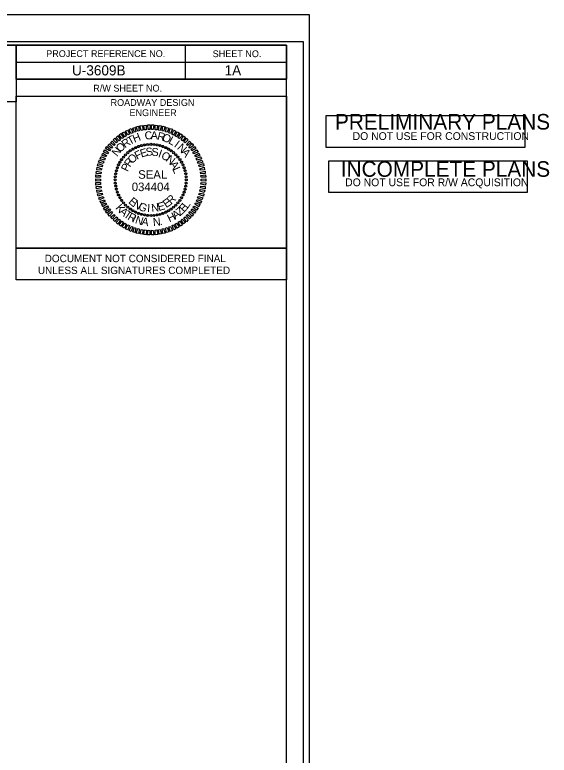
# Model space of a CAD drawing. Extents: x 1877070 to 1879304, y 464355 to 465670.
# Drawn here: x 1878829 to 1879304, y 465012 to 465670 of the extents above; entities that cross this region are included whole.
import ezdxf

# ---------------------------------------------------------------- set-up
doc = ezdxf.new("R2010")
doc.units = 0
for name, color, linetype in [('Prop AutoTurn Projected Path', 7, 'Continuous'), ('Prop Conc 2ft 6in Curb and Gutter', 7, 'Continuous'), ('Prop EOT', 7, 'Continuous'), ('Prop Horizontal Alignment', 7, 'Continuous'), ('Prop Horizontal Alignment Direction Label', 7, 'Continuous'), ('Prop Horizontal Alignment Tick Label', 7, 'Continuous'), ('Prop Horizontal Alignment Tick Small', 7, 'Continuous'), ('Prop Lane Lines', 7, 'Continuous'), ('Scratch_Level_0', 7, 'Continuous'), ('Scratch_Level_6', 7, 'Continuous')]:
    doc.layers.add(name, color=color, linetype=linetype)

# ---------------------------------------------------------------- blocks, each defined once
blk = doc.blocks.new('STICKER PRELIMINARY PLANS')
at = {"layer": 'Prop Horizontal Alignment Direction Label'}
blk.add_lwpolyline([(0, -0.47), (0, 0), (2.94, 0), (2.94, -0.47)], close=True, dxfattribs=at)
for s, height, p in [('PRELIMINARY PLANS', 0.2304, (0.13, -0.207)), ('DO NOT USE FOR CONSTRUCTION', 0.1152, (0.392, -0.361))]:
    blk.add_text(s, height=height, dxfattribs=at).set_placement(p)

msp = doc.modelspace()

# ---------------------------------------------------------------- linework, layer by layer
at = {"layer": 'Prop AutoTurn Projected Path'}
msp.add_lwpolyline([(1877069.97, 464355.13), (1879090.77, 464355.13), (1879090.77, 465669.52), (1877069.97, 465669.52)], close=True, dxfattribs=at)
at = {"layer": 'Prop Conc 2ft 6in Curb and Gutter'}
for p, q in [((1878938.83, 465552.69), (1878938.83, 465552.69)), ((1878941.47, 465553.5), (1878941.47, 465553.5)), ((1878944.23, 465554.05), (1878944.23, 465554.05)), ((1878946.93, 465554.47), (1878946.93, 465554.47)), ((1878949.7, 465554.59), (1878949.7, 465554.59)), ((1878952.47, 465554.45), (1878952.47, 465554.45)), ((1878955.19, 465554.05), (1878955.19, 465554.05)), ((1878957.84, 465553.53), (1878957.84, 465553.53)), ((1878960.5, 465552.7), (1878960.5, 465552.7)), ((1878927.31, 465545.31), (1878927.31, 465545.31)), ((1878929.36, 465547.24), (1878929.36, 465547.24)), ((1878931.53, 465548.85), (1878931.53, 465548.85)), ((1878933.9, 465550.34), (1878933.9, 465550.34)), ((1878936.33, 465551.64), (1878936.33, 465551.64)), ((1878963.04, 465551.61), (1878963.04, 465551.61)), ((1878965.52, 465550.39), (1878965.52, 465550.39)), ((1878967.81, 465548.86), (1878967.81, 465548.86)), ((1878970.05, 465547.19), (1878970.05, 465547.19)), ((1878972.03, 465545.34), (1878972.03, 465545.34)), ((1878922.26, 465538.8), (1878922.26, 465538.8)), ((1878923.79, 465541.09), (1878923.79, 465541.09)), ((1878925.46, 465543.33), (1878925.46, 465543.33)), ((1878973.96, 465543.29), (1878973.96, 465543.29)), ((1878975.57, 465541.12), (1878975.57, 465541.12)), ((1878977.06, 465538.75), (1878977.06, 465538.75)), ((1878919.95, 465533.78), (1878919.95, 465533.78)), ((1878921.04, 465536.32), (1878921.04, 465536.32)), ((1878978.36, 465536.32), (1878978.36, 465536.32)), ((1878979.41, 465533.81), (1878979.41, 465533.81)), ((1878918.2, 465525.75), (1878918.2, 465525.75)), ((1878918.6, 465528.47), (1878918.6, 465528.47)), ((1878919.12, 465531.12), (1878919.12, 465531.12)), ((1878980.22, 465531.18), (1878980.22, 465531.18)), ((1878980.77, 465528.42), (1878980.77, 465528.42)), ((1878981.19, 465525.72), (1878981.19, 465525.72)), ((1878918.06, 465522.98), (1878918.06, 465522.98)), ((1878918.18, 465520.21), (1878918.18, 465520.21)), ((1878981.16, 465520.18), (1878981.16, 465520.18)), ((1878981.3, 465522.95), (1878981.3, 465522.95)), ((1878918.6, 465517.51), (1878918.6, 465517.51)), ((1878919.15, 465514.75), (1878919.15, 465514.75)), ((1878980.25, 465514.81), (1878980.25, 465514.81)), ((1878980.77, 465517.46), (1878980.77, 465517.46)), ((1878919.95, 465512.12), (1878919.95, 465512.12)), ((1878921.01, 465509.62), (1878921.01, 465509.62)), ((1878922.31, 465507.18), (1878922.31, 465507.18)), ((1878977.11, 465507.13), (1878977.11, 465507.13)), ((1878978.32, 465509.61), (1878978.32, 465509.61)), ((1878979.41, 465512.15), (1878979.41, 465512.15)), ((1878923.8, 465504.81), (1878923.8, 465504.81)), ((1878925.41, 465502.64), (1878925.41, 465502.64)), ((1878927.34, 465500.59), (1878927.34, 465500.59)), ((1878972.06, 465500.62), (1878972.06, 465500.62)), ((1878973.91, 465502.6), (1878973.91, 465502.6)), ((1878975.57, 465504.84), (1878975.57, 465504.84)), ((1878929.32, 465498.74), (1878929.32, 465498.74)), ((1878931.56, 465497.08), (1878931.56, 465497.08)), ((1878933.85, 465495.54), (1878933.85, 465495.54)), ((1878936.33, 465494.32), (1878936.33, 465494.32)), ((1878938.87, 465493.24), (1878938.87, 465493.24)), ((1878960.53, 465493.24), (1878960.53, 465493.24)), ((1878963.03, 465494.29), (1878963.03, 465494.29)), ((1878965.47, 465495.59), (1878965.47, 465495.59)), ((1878967.84, 465497.08), (1878967.84, 465497.08)), ((1878970.01, 465498.69), (1878970.01, 465498.69)), ((1878941.53, 465492.4), (1878941.53, 465492.4)), ((1878944.18, 465491.88), (1878944.18, 465491.88)), ((1878946.9, 465491.49), (1878946.9, 465491.49)), ((1878949.67, 465491.35), (1878949.67, 465491.35)), ((1878952.44, 465491.46), (1878952.44, 465491.46)), ((1878955.14, 465491.88), (1878955.14, 465491.88)), ((1878957.9, 465492.43), (1878957.9, 465492.43))]:
    msp.add_line(p, q, dxfattribs=at)
for points in [[(1878944.25, 465567.34), (1878943.48, 465571.36), (1878945.62, 465571.65), (1878945.76, 465567.56)], [(1878947.39, 465567.71), (1878947, 465571.8), (1878949.08, 465571.77), (1878948.9, 465567.67)], [(1878950.41, 465567.7), (1878950.34, 465571.79), (1878952.42, 465571.77), (1878951.93, 465567.66)], [(1878953.57, 465567.57), (1878953.75, 465571.66), (1878955.83, 465571.32), (1878955.08, 465567.34)], [(1878926.72, 465561.3), (1878924.33, 465564.66), (1878926.26, 465565.7), (1878927.9, 465562.08)], [(1878929.4, 465562.86), (1878927.32, 465566.35), (1878929.26, 465567.27), (1878930.77, 465563.45)], [(1878932.15, 465564.23), (1878930.44, 465567.85), (1878932.32, 465568.64), (1878933.71, 465564.64)], [(1878935.21, 465565.29), (1878933.7, 465569.05), (1878935.64, 465569.65), (1878936.53, 465565.76)], [(1878938.22, 465566.16), (1878936.83, 465570.11), (1878938.96, 465570.59), (1878939.54, 465566.5)], [(1878941.23, 465566.91), (1878940.15, 465570.92), (1878942.23, 465571.15), (1878942.74, 465567.12)], [(1878956.6, 465567.11), (1878957.09, 465571.15), (1878959.18, 465570.88), (1878958.11, 465566.95)], [(1878959.82, 465566.48), (1878960.38, 465570.58), (1878962.53, 465570.12), (1878961.15, 465566.19)], [(1878962.86, 465565.71), (1878963.73, 465569.63), (1878965.7, 465569.04), (1878964.19, 465565.29)], [(1878965.71, 465564.63), (1878967.09, 465568.62), (1878968.87, 465567.9), (1878967.17, 465564.21)], [(1878968.57, 465563.48), (1878970.07, 465567.22), (1878972.04, 465566.38), (1878969.96, 465562.81)], [(1878971.49, 465562.08), (1878973.12, 465565.7), (1878975.03, 465564.67), (1878972.7, 465561.35)], [(1878919.13, 465555.75), (1878916.31, 465558.47), (1878917.8, 465560.01), (1878920.31, 465556.65)], [(1878921.61, 465557.75), (1878918.85, 465560.72), (1878920.53, 465562.08), (1878922.8, 465558.59)], [(1878923.97, 465559.68), (1878921.59, 465562.85), (1878923.2, 465564.07), (1878925.35, 465560.46)], [(1878973.97, 465560.43), (1878976.11, 465564.12), (1878977.77, 465562.82), (1878975.37, 465559.7)], [(1878976.59, 465558.58), (1878978.86, 465562.09), (1878980.52, 465560.73), (1878977.8, 465557.72)], [(1878979.01, 465556.67), (1878981.54, 465559.99), (1878983.08, 465558.51), (1878980.23, 465555.75)], [(1878913.08, 465548.65), (1878909.64, 465550.74), (1878910.81, 465552.58), (1878913.88, 465549.87)], [(1878914.93, 465551.08), (1878911.61, 465553.48), (1878912.97, 465555.14), (1878915.79, 465552.23)], [(1878917.09, 465553.51), (1878913.83, 465556.04), (1878915.38, 465557.51), (1878918.08, 465554.54)], [(1878981.32, 465554.51), (1878983.98, 465557.51), (1878985.51, 465556.03), (1878982.28, 465553.52)], [(1878983.56, 465552.28), (1878986.41, 465555.16), (1878987.76, 465553.49), (1878984.47, 465551.04)], [(1878985.49, 465549.86), (1878988.53, 465552.56), (1878989.76, 465550.75), (1878986.27, 465548.67)], [(1878909.77, 465543.37), (1878906.16, 465544.88), (1878907.07, 465546.85), (1878910.51, 465544.58)], [(1878911.24, 465546.1), (1878907.68, 465547.93), (1878908.9, 465549.72), (1878912.22, 465547.25)], [(1878987.18, 465547.3), (1878990.47, 465549.75), (1878991.7, 465547.89), (1878988.08, 465546.06)], [(1878988.86, 465544.56), (1878992.35, 465546.83), (1878993.2, 465544.89), (1878989.64, 465543.38)], [(1878907.35, 465537.66), (1878903.43, 465538.72), (1878904.21, 465540.69), (1878908.02, 465538.99)], [(1878908.56, 465540.45), (1878904.63, 465541.83), (1878905.54, 465543.8), (1878909.17, 465541.85)], [(1878990.17, 465541.88), (1878993.85, 465543.83), (1878994.71, 465541.83), (1878990.82, 465540.5)], [(1878991.35, 465538.94), (1878995.17, 465540.64), (1878995.89, 465538.7), (1878992.01, 465537.63)], [(1878905.69, 465531.58), (1878901.78, 465532.02), (1878902.19, 465534.17), (1878906.18, 465532.91)], [(1878906.46, 465534.62), (1878902.54, 465535.37), (1878902.95, 465537.45), (1878906.94, 465535.95)], [(1878992.41, 465535.93), (1878996.42, 465537.45), (1878996.83, 465535.38), (1878992.88, 465534.62)], [(1878993.22, 465532.92), (1878997.17, 465534.19), (1878997.58, 465532.05), (1878993.62, 465531.61)], [(1878904.98, 465525.33), (1878900.89, 465525.39), (1878900.98, 465527.47), (1878905.08, 465526.85)], [(1878905.25, 465528.36), (1878901.21, 465528.67), (1878901.42, 465530.81), (1878905.54, 465529.88)], [(1878993.84, 465529.91), (1878997.92, 465530.86), (1878998.15, 465528.72), (1878994.12, 465528.4)], [(1878994.27, 465526.89), (1878998.36, 465527.47), (1878998.52, 465525.33), (1878994.43, 465525.38)], [(1878904.98, 465522.18), (1878900.89, 465521.92), (1878900.85, 465524.07), (1878904.95, 465523.7)], [(1878905.09, 465519.04), (1878901.01, 465518.46), (1878900.85, 465520.6), (1878904.94, 465520.55)], [(1878994.38, 465520.6), (1878998.48, 465520.54), (1878998.39, 465518.46), (1878994.28, 465519.08)], [(1878994.39, 465523.75), (1878998.48, 465524.01), (1878998.52, 465521.87), (1878994.42, 465522.24)], [(1878905.53, 465516.02), (1878901.45, 465515.07), (1878901.22, 465517.21), (1878905.25, 465517.53)], [(1878906.15, 465513.01), (1878902.2, 465511.74), (1878901.78, 465513.88), (1878905.74, 465514.32)], [(1878993.67, 465514.35), (1878997.59, 465513.91), (1878997.18, 465511.76), (1878993.19, 465513.02)], [(1878994.12, 465517.57), (1878998.16, 465517.26), (1878997.94, 465515.12), (1878993.83, 465516.05)], [(1878906.95, 465510), (1878902.95, 465508.48), (1878902.53, 465510.55), (1878906.49, 465511.31)], [(1878908.01, 465507), (1878904.2, 465505.29), (1878903.47, 465507.23), (1878907.36, 465508.31)], [(1878992.02, 465508.27), (1878995.94, 465507.21), (1878995.16, 465505.24), (1878991.35, 465506.94)], [(1878992.91, 465511.31), (1878996.83, 465510.56), (1878996.42, 465508.48), (1878992.43, 465509.98)], [(1878909.2, 465504.06), (1878905.52, 465502.1), (1878904.66, 465504.1), (1878908.54, 465505.43)], [(1878910.51, 465501.37), (1878907.02, 465499.1), (1878906.16, 465501.04), (1878909.73, 465502.55)], [(1878912.19, 465498.63), (1878908.9, 465496.18), (1878907.67, 465498.04), (1878911.29, 465499.87)], [(1878988.13, 465499.83), (1878991.69, 465498), (1878990.46, 465496.22), (1878987.14, 465498.68)], [(1878989.6, 465502.56), (1878993.21, 465501.05), (1878992.3, 465499.08), (1878988.86, 465501.35)], [(1878990.81, 465505.48), (1878994.73, 465504.1), (1878993.82, 465502.13), (1878990.2, 465504.08)], [(1878913.87, 465496.07), (1878910.83, 465493.38), (1878909.61, 465495.18), (1878913.1, 465497.26)], [(1878915.81, 465493.65), (1878912.96, 465490.77), (1878911.61, 465492.44), (1878914.9, 465494.9)], [(1878984.44, 465494.85), (1878987.76, 465492.45), (1878986.4, 465490.79), (1878983.58, 465493.7)], [(1878986.29, 465497.28), (1878989.72, 465495.19), (1878988.56, 465493.35), (1878985.49, 465496.07)], [(1878918.05, 465491.42), (1878915.39, 465488.42), (1878913.85, 465489.9), (1878917.09, 465492.41)], [(1878920.35, 465489.26), (1878917.83, 465485.94), (1878916.29, 465487.42), (1878919.14, 465490.18)], [(1878922.78, 465487.35), (1878920.51, 465483.85), (1878918.85, 465485.2), (1878921.57, 465488.21)], [(1878925.4, 465485.5), (1878923.26, 465481.81), (1878921.59, 465483.11), (1878924, 465486.24)], [(1878975.39, 465486.25), (1878977.78, 465483.08), (1878976.16, 465481.86), (1878974.02, 465485.47)], [(1878977.75, 465488.18), (1878980.51, 465485.21), (1878978.84, 465483.86), (1878976.57, 465487.34)], [(1878980.24, 465490.18), (1878983.06, 465487.46), (1878981.57, 465485.92), (1878979.06, 465489.28)], [(1878982.28, 465492.42), (1878985.53, 465489.89), (1878983.99, 465488.42), (1878981.29, 465491.39)], [(1878927.88, 465483.85), (1878926.24, 465480.23), (1878924.34, 465481.27), (1878926.67, 465484.58)], [(1878930.8, 465482.45), (1878929.29, 465478.71), (1878927.33, 465479.55), (1878929.4, 465483.12)], [(1878933.66, 465481.3), (1878932.28, 465477.31), (1878930.5, 465478.04), (1878932.2, 465481.72)], [(1878936.51, 465480.22), (1878935.63, 465476.3), (1878933.67, 465476.89), (1878935.18, 465480.64)], [(1878939.55, 465479.45), (1878938.99, 465475.35), (1878936.84, 465475.82), (1878938.22, 465479.75)], [(1878961.15, 465479.77), (1878962.54, 465475.82), (1878960.41, 465475.35), (1878959.83, 465479.43)], [(1878964.15, 465480.64), (1878965.67, 465476.89), (1878963.73, 465476.29), (1878962.84, 465480.18)], [(1878967.22, 465481.7), (1878968.92, 465478.08), (1878967.05, 465477.29), (1878965.66, 465481.29)], [(1878969.97, 465483.07), (1878972.05, 465479.58), (1878970.11, 465478.66), (1878968.59, 465482.48)], [(1878972.65, 465484.63), (1878975.04, 465481.27), (1878973.11, 465480.23), (1878971.47, 465483.85)], [(1878942.77, 465478.82), (1878942.27, 465474.78), (1878940.19, 465475.06), (1878941.26, 465478.98)], [(1878945.8, 465478.37), (1878945.62, 465474.27), (1878943.54, 465474.61), (1878944.29, 465478.59)], [(1878948.95, 465478.23), (1878949.03, 465474.14), (1878946.95, 465474.17), (1878947.44, 465478.27)], [(1878951.98, 465478.22), (1878952.36, 465474.13), (1878950.28, 465474.16), (1878950.46, 465478.26)], [(1878955.12, 465478.59), (1878955.88, 465474.57), (1878953.75, 465474.28), (1878953.61, 465478.38)], [(1878958.14, 465479.02), (1878959.21, 465475.01), (1878957.14, 465474.78), (1878956.63, 465478.81)]]:
    msp.add_lwpolyline(points, close=True, dxfattribs=at)
for centre, major_axis in [((1878936.33, 465551.6), (-0.383, 0.822)), ((1878938.88, 465552.65), (-0.31, 0.852)), ((1878941.51, 465553.48), (-0.235, 0.876)), ((1878944.2, 465554.08), (-0.157, 0.893)), ((1878946.93, 465554.43), (-0.079, 0.903)), ((1878949.68, 465554.56), (0, 0.907)), ((1878952.44, 465554.43), (0.079, 0.903)), ((1878955.17, 465554.08), (0.157, 0.893)), ((1878957.86, 465553.48), (0.235, 0.876)), ((1878960.49, 465552.65), (0.31, 0.852)), ((1878963.03, 465551.6), (0.383, 0.822)), ((1878927.35, 465545.3), (-0.641, 0.641)), ((1878929.38, 465547.16), (-0.583, 0.695)), ((1878931.56, 465548.84), (-0.52, 0.743)), ((1878933.89, 465550.32), (-0.453, 0.785)), ((1878965.48, 465550.32), (0.453, 0.785)), ((1878967.8, 465548.84), (0.52, 0.743)), ((1878969.99, 465547.16), (0.583, 0.695)), ((1878972.02, 465545.3), (0.641, 0.641)), ((1878922.33, 465538.76), (-0.785, 0.453)), ((1878923.81, 465541.08), (-0.743, 0.52)), ((1878925.48, 465543.27), (-0.695, 0.583)), ((1878973.88, 465543.27), (0.695, 0.583)), ((1878975.56, 465541.08), (0.743, 0.52)), ((1878977.04, 465538.76), (0.785, 0.453)), ((1878919.17, 465531.14), (-0.876, 0.235)), ((1878920, 465533.77), (-0.852, 0.31)), ((1878921.05, 465536.32), (-0.822, 0.383)), ((1878978.31, 465536.32), (0.822, 0.383)), ((1878979.37, 465533.77), (0.852, 0.31)), ((1878980.2, 465531.14), (0.876, 0.235)), ((1878918.21, 465525.72), (-0.903, 0.079)), ((1878918.57, 465528.45), (-0.893, 0.157)), ((1878980.79, 465528.45), (0.893, 0.157)), ((1878981.15, 465525.72), (0.903, 0.079)), ((1878918.09, 465522.97), (-0.907, 0)), ((1878918.21, 465520.21), (-0.903, -0.079)), ((1878981.15, 465520.21), (0.903, -0.079)), ((1878981.27, 465522.97), (0.907, 0)), ((1878918.57, 465517.48), (-0.893, -0.157)), ((1878919.17, 465514.79), (-0.876, -0.235)), ((1878920, 465512.16), (-0.852, -0.31)), ((1878979.37, 465512.16), (0.852, -0.31)), ((1878980.2, 465514.79), (0.876, -0.235)), ((1878980.79, 465517.48), (0.893, -0.157)), ((1878921.05, 465509.61), (-0.822, -0.383)), ((1878922.33, 465507.17), (-0.785, -0.453)), ((1878923.81, 465504.85), (-0.743, -0.52)), ((1878975.56, 465504.85), (0.743, -0.52)), ((1878977.04, 465507.17), (0.785, -0.453)), ((1878978.31, 465509.62), (0.822, -0.383)), ((1878925.49, 465502.66), (-0.695, -0.583)), ((1878927.35, 465500.63), (-0.641, -0.641)), ((1878929.38, 465498.77), (-0.583, -0.695)), ((1878969.99, 465498.77), (0.583, -0.695)), ((1878972.02, 465500.63), (0.641, -0.641)), ((1878973.88, 465502.66), (0.695, -0.583)), ((1878931.57, 465497.09), (-0.52, -0.743)), ((1878933.89, 465495.61), (-0.453, -0.785)), ((1878936.33, 465494.34), (-0.383, -0.822)), ((1878938.88, 465493.28), (-0.31, -0.852)), ((1878941.51, 465492.45), (-0.235, -0.876)), ((1878944.2, 465491.86), (-0.157, -0.893)), ((1878955.17, 465491.86), (0.157, -0.893)), ((1878957.86, 465492.45), (0.235, -0.876)), ((1878960.49, 465493.28), (0.31, -0.852)), ((1878963.03, 465494.34), (0.383, -0.822)), ((1878965.48, 465495.61), (0.453, -0.785)), ((1878967.8, 465497.09), (0.52, -0.743)), ((1878946.93, 465491.5), (-0.079, -0.903)), ((1878949.68, 465491.38), (0, -0.907)), ((1878952.44, 465491.5), (0.079, -0.903))]:
    msp.add_ellipse(centre, major_axis=major_axis, ratio=0.999708, dxfattribs=at)
at = {"layer": 'Prop EOT'}
msp.add_line((1877269.83, 465642.52), (1879070.4, 465642.53), dxfattribs=at)
at = {"layer": 'Prop Horizontal Alignment Tick Label'}
for p, q in [((1878830.25, 465434.21), (1878830.25, 465462.42)), ((1878830.25, 465462.42), (1879070.37, 465462.42)), ((1878830.25, 465434.21), (1878830.25, 465462.42)), ((1878830.25, 465462.42), (1879070.37, 465462.42)), ((1879070.37, 465462.4), (1879070.37, 465434.19)), ((1879070.37, 465462.4), (1879070.37, 465434.19)), ((1879070.37, 465434.21), (1878830.25, 465434.21)), ((1879070.37, 465434.21), (1878830.25, 465434.21))]:
    msp.add_line(p, q, dxfattribs=at)
at = {"layer": 'Prop Horizontal Alignment Tick Small'}
msp.add_lwpolyline([(1878687.04, 465642.53), (1878830.24, 465642.55), (1878830.24, 465592.19), (1878687.05, 465592.17)], close=True, dxfattribs=at)
at = {"layer": 'Prop Lane Lines'}
msp.add_lwpolyline([(1877085.58, 464379.14), (1879085.37, 464379.14), (1879085.37, 465645.52), (1877085.58, 465645.52)], close=True, dxfattribs=at)
at = {"layer": 'Scratch_Level_0'}
for p, q in [((1878980.3, 465642.46), (1878980.36, 465612.45)), ((1878830.22, 465627.48), (1879070.35, 465627.47)), ((1878830.24, 465612.43), (1879070.35, 465612.46)), ((1878830.24, 465612.43), (1879070.35, 465612.46)), ((1878830.24, 465612.43), (1878830.24, 465597.44)), ((1878830.24, 465612.43), (1878830.24, 465597.44)), ((1878830.24, 465612.43), (1878830.24, 465597.44))]:
    msp.add_line(p, q, dxfattribs=at)
for points in [[(1879070.37, 465642.52), (1877269.83, 465642.52), (1877269.83, 464382.14), (1879070.37, 464382.14)], [(1878830.24, 465642.55), (1879070.4, 465642.53), (1879070.35, 465612.46), (1878830.24, 465612.43)], [(1878830.24, 465597.44), (1879070.37, 465597.44), (1879070.37, 465462.4), (1878830.24, 465462.4)]]:
    msp.add_lwpolyline(points, close=True, dxfattribs=at)
at = {"layer": 'Scratch_Level_6'}
msp.add_lwpolyline([(1879107.72, 465511.71), (1879107.72, 465539.91), (1879284.16, 465539.92), (1879284.16, 465511.71)], close=True, dxfattribs=at)

# ---------------------------------------------------------------- block references
at = {"layer": 'Prop Horizontal Alignment', "xscale": 60.01538725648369, "yscale": 60.01538725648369}
msp.add_blockref('STICKER PRELIMINARY PLANS', (1879105.47, 465580.09), dxfattribs=at)

# ---------------------------------------------------------------- texts
at = {"layer": 'Prop Conc 2ft 6in Curb and Gutter'}
for s, height, rotation, p in [('U-3609B', 9.003, 0, (1878879.78, 465615.75)), ('C', 7.1, 7.22052, (1878944.72, 465558.59)), ('A', 7.1, 0.02097, (1878949.68, 465559.06)), ('R', 7.1, 345.62175, (1878954.98, 465558.9)), ('R', 7.1, 36.02115, (1878926.9, 465550.91)), ('T', 7.1, 28.82042, (1878931.13, 465553.76)), ('H', 7.1, 21.62013, (1878935.19, 465555.91)), ('O', 7.1, 338.42181, (1878959.21, 465558.03)), ('L', 7.1, 331.22152, (1878964.79, 465555.79)), ('N', 7.1, 50.42415, (1878919.79, 465543.23)), ('O', 7.1, 43.22239, (1878922.62, 465546.93)), ('S', 7.1, 8.25626, (1878945.79, 465544.12)), ('I', 7.1, 324.02079, (1878969.95, 465552.86)), ('N', 7.1, 316.81956, (1878972.69, 465550.96)), ('O', 7.1, 45.68189, (1878933.38, 465536.98)), ('F', 7.1, 26.96768, (1878937.47, 465540.77)), ('E', 7.1, 17.61172, (1878941.47, 465542.73)), ('S', 7.1, 358.90105, (1878950.32, 465544.27)), ('I', 7.1, 340.19025, (1878955.75, 465543.48)), ('O', 7.1, 330.83413, (1878958.28, 465542.64)), ('N', 7.1, 321.47726, (1878962.55, 465540.2)), ('A', 7.1, 309.6178, (1878976.47, 465547.31)), ('R', 7.1, 55.0403, (1878931.23, 465533.85)), ('A', 7.1, 302.76092, (1878966.19, 465536.98)), ('P', 7.1, 64.39954, (1878929.28, 465529.79)), ('L', 7.1, 293.4015, (1878968.73, 465532.68)), ('SEAL', 7.555, 0.00065, (1878938.52, 465524.03)), ('034404', 7.557, 0.00065, (1878932.8, 465513.05)), ('E', 7.1, 319.27754, (1878929.38, 465502.9)), ('E', 7.1, 34.12474, (1878963.41, 465497.88)), ('R', 7.1, 43.48206, (1878967.83, 465500.92)), ('K', 7.1, 311.16864, (1878917.94, 465497.83)), ('N', 7.1, 328.6346, (1878933.21, 465499.56)), ('G', 7.1, 337.99089, (1878938.05, 465496.81)), ('I', 7.1, 356.70185, (1878946.34, 465494.56)), ('N', 7.1, 6.05704, (1878950.56, 465494.45)), ('E', 7.1, 15.41241, (1878956.78, 465495.31)), ('Z', 7.1, 41.58545, (1878975.8, 465490.65)), ('E', 7.1, 48.12493, (1878979.32, 465493.75)), ('L', 7.1, 54.29971, (1878982.29, 465497.03)), ('A', 7.1, 318.07284, (1878921.2, 465494.1)), ('T', 7.1, 325.32255, (1878925.07, 465490.64)), ('R', 7.1, 331.30538, (1878928.58, 465488.18)), ('H', 7.1, 26.37579, (1878966.44, 465485.13)), ('A', 7.1, 34.33573, (1878971.52, 465487.71)), ('I', 7.1, 337.71049, (1878932.6, 465485.96)), ('N', 7.1, 341.83137, (1878935.3, 465484.77)), ('A', 7.1, 350.252, (1878941.06, 465482.97)), ('N', 7.1, 5.59602, (1878951.97, 465481.91)), ('.', 7.1, 14.01664, (1878957.97, 465482.58))]:
    msp.add_text(s, height=height, rotation=rotation, dxfattribs=at).set_placement(p)
msp.add_text('1A ', height=9.003, dxfattribs=at).set_placement((1879015.29, 465615.81))
at = {"layer": 'Prop Horizontal Alignment Tick Label'}
for s, p in [('DOCUMENT NOT CONSIDERED FINAL', (1878855.54, 465450)), ('DOCUMENT NOT CONSIDERED FINAL', (1878855.54, 465450)), ('UNLESS ALL SIGNATURES COMPLETED', (1878849.46, 465439.44)), ('UNLESS ALL SIGNATURES COMPLETED', (1878849.46, 465439.44))]:
    msp.add_text(s, height=6.602, dxfattribs=at).set_placement(p)
at = {"layer": 'Scratch_Level_0'}
for s, height, p in [('PROJECT REFERENCE NO.', 6.0019, (1878856.88, 465632.07)), ('SHEET NO.', 6.002, (1879004.72, 465631.94)), ('R/W SHEET NO.', 6.0019, (1878898.66, 465601.4)), ('ROADWAY DESIGN', 6.0019, (1878914.02, 465588.68)), ('ENGINEER', 6.002, (1878930.81, 465579.63))]:
    msp.add_text(s, height=height, rotation=0, dxfattribs=at).set_placement(p)
at = {"layer": 'Scratch_Level_6'}
for s, height, p in [('INCOMPLETE PLANS', 13.8275, (1879118.46, 465525.75)), ('DO NOT USE FOR R/W ACQUISITION', 6.9138, (1879122.36, 465517.41))]:
    msp.add_text(s, height=height, rotation=0.00094, dxfattribs=at).set_placement(p)

doc.saveas('drawing.dxf')
